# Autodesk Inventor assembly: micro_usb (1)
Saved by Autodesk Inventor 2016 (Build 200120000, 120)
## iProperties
Created: 2016-09
Part Number: micro_usb (1)
Document SubType Name: Assembly
Designer: Administrator
Author: Administrator
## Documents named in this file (4)
- c:\worker\convert-fusion-aug-2016\tmp\job-1\13\output\files\2055b865-881d-4af8-ae30-e7b46ec3c804\micro_usb (1).iam
- c:\worker\convert-fusion-aug-2016\tmp\job-1\13\output\files\2055b865-881d-4af8-ae30-e7b46ec3c804\Group#12 (1).ipt
- c:\worker\convert-fusion-aug-2016\tmp\job-1\13\output\files\2055b865-881d-4af8-ae30-e7b46ec3c804\micro_usb_plastic (1).ipt
- c:\worker\convert-fusion-aug-2016\tmp\job-1\13\output\files\2055b865-881d-4af8-ae30-e7b46ec3c804\micro_usb_shell (1).ipt
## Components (7 placed, 3 different names)
1. Group#12 (1):1
2. micro_usb_plastic (1):1
3. micro_usb_shell (1):1
4. Group#12 (1):2
5. Group#12 (1):3
6. Group#12 (1):4
7. Group#12 (1):5
